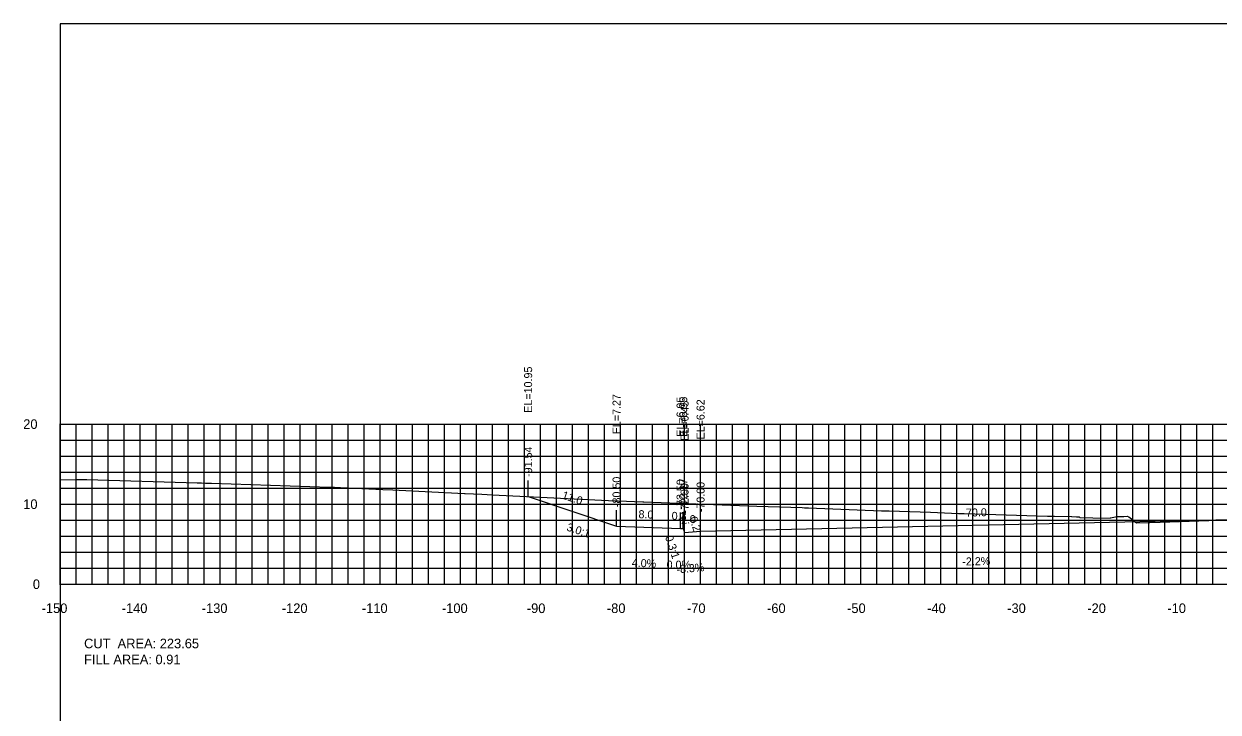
# Model space of a CAD drawing. Extents: x 1797419 to 1809236, y 248759 to 251512.
# Drawn here: x 1804856.5 to 1805005.6, y 250521.3 to 250607.3 of the extents above; entities that cross this region are included whole.
import ezdxf

# ---------------------------------------------------------------- set-up
doc = ezdxf.new("R2010")
doc.units = 0
for name, color, linetype in [('10', 7, 'Continuous'), ('3', 7, 'Continuous'), ('31', 7, 'Continuous'), ('4', 7, 'Continuous'), ('60', 7, 'Continuous'), ('ANNO-TXT', 7, 'Continuous'), ('CL-CNST', 7, 'Continuous'), ('Level 62', 7, 'Continuous'), ('M-ROADS', 7, 'Continuous')]:
    doc.layers.add(name, color=color, linetype=linetype)

msp = doc.modelspace()

# ---------------------------------------------------------------- linework, layer by layer
for p, q in [((1804919.46, 250548.21), (1804919.46, 250550.21)), ((1804930.5, 250544.52), (1804930.5, 250546.52)), ((1804938.5, 250544.2), (1804938.5, 250546.2)), ((1804938.83, 250544.2), (1804938.83, 250546.2)), ((1804939, 250543.7), (1804939, 250545.7)), ((1804941, 250543.87), (1804941, 250545.87))]:
    msp.add_line(p, q)
msp.add_lwpolyline([(1804861, 250417.26), (1805161, 250417.26), (1805161, 250607.26), (1804861, 250607.26)], close=True)
at = {"layer": '60'}
for p, q in [((1804860.94, 250557.26), (1804861, 250557.26)), ((1804861, 250537.26), (1804861, 250557.26)), ((1804860.94, 250547.26), (1804861, 250547.26)), ((1804860.94, 250537.26), (1804861, 250537.26)), ((1804861, 250537.26), (1805161, 250537.26)), ((1804861, 250537.2), (1804861, 250537.26)), ((1804871, 250537.2), (1804871, 250537.26)), ((1804881, 250537.2), (1804881, 250537.26)), ((1804891, 250537.2), (1804891, 250537.26)), ((1804901, 250537.2), (1804901, 250537.26)), ((1804911, 250537.2), (1804911, 250537.26)), ((1804921, 250537.2), (1804921, 250537.26)), ((1804931, 250537.2), (1804931, 250537.26)), ((1804941, 250537.2), (1804941, 250537.26)), ((1804951, 250537.2), (1804951, 250537.26)), ((1804961, 250537.2), (1804961, 250537.26)), ((1804971, 250537.2), (1804971, 250537.26)), ((1804981, 250537.2), (1804981, 250537.26)), ((1804991, 250537.2), (1804991, 250537.26)), ((1805001, 250537.2), (1805001, 250537.26))]:
    msp.add_line(p, q, dxfattribs=at)
at = {"layer": 'CL-CNST'}
msp.add_lwpolyline([(1804919.46, 250548.21), (1804930.5, 250544.52), (1804938.5, 250544.2), (1804938.83, 250544.2), (1804939, 250543.7), (1804941, 250543.87), (1805011, 250545.41), (1805081, 250543.89), (1805083, 250543.73), (1805083.17, 250544.23), (1805083.5, 250544.23), (1805085.5, 250544.31), (1805090.5, 250544.41), (1805091.5, 250544.45), (1805094.63, 250545.49)], dxfattribs=at)
at = {"layer": 'Level 62'}
for p, q in [((1804861, 250557.26), (1805161, 250557.26)), ((1804861, 250537.26), (1804861, 250557.26)), ((1804863, 250537.26), (1804863, 250557.26)), ((1804865, 250537.26), (1804865, 250557.26)), ((1804867, 250537.26), (1804867, 250557.26)), ((1804869, 250537.26), (1804869, 250557.26)), ((1804871, 250537.26), (1804871, 250557.26)), ((1804873, 250537.26), (1804873, 250557.26)), ((1804875, 250537.26), (1804875, 250557.26)), ((1804877, 250537.26), (1804877, 250557.26)), ((1804879, 250537.26), (1804879, 250557.26)), ((1804881, 250537.26), (1804881, 250557.26)), ((1804883, 250537.26), (1804883, 250557.26)), ((1804885, 250537.26), (1804885, 250557.26)), ((1804887, 250537.26), (1804887, 250557.26)), ((1804889, 250537.26), (1804889, 250557.26)), ((1804891, 250537.26), (1804891, 250557.26)), ((1804893, 250537.26), (1804893, 250557.26)), ((1804895, 250537.26), (1804895, 250557.26)), ((1804897, 250537.26), (1804897, 250557.26)), ((1804899, 250537.26), (1804899, 250557.26)), ((1804901, 250537.26), (1804901, 250557.26)), ((1804903, 250537.26), (1804903, 250557.26)), ((1804905, 250537.26), (1804905, 250557.26)), ((1804907, 250537.26), (1804907, 250557.26)), ((1804909, 250537.26), (1804909, 250557.26)), ((1804911, 250537.26), (1804911, 250557.26)), ((1804913, 250537.26), (1804913, 250557.26)), ((1804915, 250537.26), (1804915, 250557.26)), ((1804917, 250537.26), (1804917, 250557.26)), ((1804919, 250537.26), (1804919, 250557.26)), ((1804921, 250537.26), (1804921, 250557.26)), ((1804923, 250537.26), (1804923, 250557.26)), ((1804925, 250537.26), (1804925, 250557.26)), ((1804927, 250537.26), (1804927, 250557.26)), ((1804929, 250537.26), (1804929, 250557.26)), ((1804931, 250537.26), (1804931, 250557.26)), ((1804933, 250537.26), (1804933, 250557.26)), ((1804935, 250537.26), (1804935, 250557.26)), ((1804937, 250537.26), (1804937, 250557.26)), ((1804939, 250537.26), (1804939, 250557.26)), ((1804941, 250537.26), (1804941, 250557.26)), ((1804943, 250537.26), (1804943, 250557.26)), ((1804945, 250537.26), (1804945, 250557.26)), ((1804947, 250537.26), (1804947, 250557.26)), ((1804949, 250537.26), (1804949, 250557.26)), ((1804951, 250537.26), (1804951, 250557.26)), ((1804953, 250537.26), (1804953, 250557.26)), ((1804955, 250537.26), (1804955, 250557.26)), ((1804957, 250537.26), (1804957, 250557.26)), ((1804959, 250537.26), (1804959, 250557.26)), ((1804961, 250537.26), (1804961, 250557.26)), ((1804963, 250537.26), (1804963, 250557.26)), ((1804965, 250537.26), (1804965, 250557.26)), ((1804967, 250537.26), (1804967, 250557.26)), ((1804969, 250537.26), (1804969, 250557.26)), ((1804971, 250537.26), (1804971, 250557.26)), ((1804973, 250537.26), (1804973, 250557.26)), ((1804975, 250537.26), (1804975, 250557.26)), ((1804977, 250537.26), (1804977, 250557.26)), ((1804979, 250537.26), (1804979, 250557.26)), ((1804981, 250537.26), (1804981, 250557.26)), ((1804983, 250537.26), (1804983, 250557.26)), ((1804985, 250537.26), (1804985, 250557.26)), ((1804987, 250537.26), (1804987, 250557.26)), ((1804989, 250537.26), (1804989, 250557.26)), ((1804991, 250537.26), (1804991, 250557.26)), ((1804993, 250537.26), (1804993, 250557.26)), ((1804995, 250537.26), (1804995, 250557.26)), ((1804997, 250537.26), (1804997, 250557.26)), ((1804999, 250537.26), (1804999, 250557.26)), ((1805001, 250537.26), (1805001, 250557.26)), ((1805003, 250537.26), (1805003, 250557.26)), ((1805005, 250537.26), (1805005, 250557.26)), ((1804861, 250555.26), (1805161, 250555.26)), ((1804861, 250553.26), (1805161, 250553.26)), ((1804861, 250551.26), (1805161, 250551.26)), ((1804861, 250549.26), (1805161, 250549.26)), ((1804861, 250547.26), (1805161, 250547.26)), ((1804861, 250545.26), (1805161, 250545.26)), ((1804861, 250543.26), (1805161, 250543.26)), ((1804861, 250541.26), (1805161, 250541.26)), ((1804861, 250539.26), (1805161, 250539.26)), ((1804861, 250537.26), (1805161, 250537.26))]:
    msp.add_line(p, q, dxfattribs=at)
at = {"layer": 'M-ROADS'}
msp.add_lwpolyline([(1804861, 250550.31), (1804862.94, 250550.35), (1804863.07, 250550.35), (1804863.07, 250550.35), (1804863.08, 250550.36), (1804863.37, 250550.36), (1804863.42, 250550.36), (1804863.76, 250550.36), (1804864.1, 250550.35), (1804864.35, 250550.34), (1804878.12, 250549.93), (1804878.67, 250549.92), (1804878.68, 250549.92), (1804879.18, 250549.9), (1804879.83, 250549.89), (1804879.9, 250549.89), (1804894.66, 250549.38), (1804895.19, 250549.38), (1804895.26, 250549.38), (1804896.04, 250549.35), (1804901.32, 250549.09), (1804902.58, 250549.04), (1804903.36, 250549.01), (1804911.53, 250548.59), (1804911.59, 250548.58), (1804913.68, 250548.49), (1804914.99, 250548.42), (1804930.33, 250547.69), (1804930.38, 250547.69), (1804930.69, 250547.69), (1804933.79, 250547.55), (1804933.92, 250547.54), (1804948.01, 250547.03), (1804953.68, 250546.83), (1804953.98, 250546.82), (1804954.47, 250546.81), (1804963.6, 250546.44), (1804964.09, 250546.43), (1804964.57, 250546.42), (1804969.7, 250546.25), (1804973.23, 250546.1), (1804973.52, 250546.09), (1804973.92, 250546.08), (1804977.89, 250545.95), (1804984.34, 250545.77), (1804984.63, 250545.77), (1804985.22, 250545.76), (1804987.31, 250545.73), (1804987.36, 250545.73), (1804987.97, 250545.69), (1804988.29, 250545.69), (1804988.35, 250545.58), (1804989.98, 250545.54), (1804992.17, 250545.53), (1804992.21, 250545.57), (1804992.82, 250545.68), (1804993.08, 250545.72), (1804993.31, 250545.72), (1804993.43, 250545.72), (1804993.65, 250545.72), (1804993.79, 250545.72), (1804993.86, 250545.71), (1804994.3, 250545.76), (1804994.48, 250545.68), (1804994.83, 250545.42), (1804995.09, 250545.2), (1804995.43, 250544.93), (1804996.95, 250544.96), (1804996.99, 250544.96), (1804997.12, 250544.98), (1804997.13, 250544.98), (1804998.4, 250545.03), (1805009.31, 250545.39)], dxfattribs=at)

# ---------------------------------------------------------------- texts
for s, rotation, p in [('3.0:1', 341.5651, (1804924.19, 250543.99)), ('0.3:1', 288.4353, (1804936.55, 250543.16))]:
    msp.add_text(s, height=1, rotation=rotation).set_placement(p)
at = {"layer": '10'}
for s, p in [('-150', (1804858.7, 250533.66)), ('-140', (1804868.7, 250533.66)), ('-130', (1804878.7, 250533.66)), ('-120', (1804888.7, 250533.66)), ('-110', (1804898.7, 250533.66)), ('-100', (1804908.7, 250533.66)), ('-90', (1804919.3, 250533.66)), ('-80', (1804929.3, 250533.66)), ('-70', (1804939.3, 250533.66)), ('-60', (1804949.3, 250533.66)), ('-50', (1804959.3, 250533.66)), ('-40', (1804969.3, 250533.66)), ('-30', (1804979.3, 250533.66)), ('-20', (1804989.3, 250533.66)), ('-10', (1804999.3, 250533.66))]:
    msp.add_text(s, height=1.2, dxfattribs=at).set_placement(p)
at = {"layer": '3'}
for s, p in [('EL=10.95', (1804919.96, 250558.68)), ('EL=7.27', (1804931, 250555.99)), ('EL=6.95', (1804939, 250555.67)), ('EL=6.95', (1804939.33, 250555.67)), ('EL=6.62', (1804941.5, 250555.34)), ('EL=6.45', (1804939.5, 250555.17)), ('-91.54', (1804919.96, 250550.66)), ('-80.50', (1804931, 250546.9)), ('-72.50', (1804939, 250546.58)), ('-72.17', (1804939.33, 250546.66)), ('-72.00', (1804939.5, 250546.08)), ('-70.00', (1804941.5, 250546.25))]:
    msp.add_text(s, height=1, rotation=90, dxfattribs=at).set_placement(p)
at = {"layer": '31'}
for s, p in [('20', (1804856.4, 250556.66)), ('10', (1804856.4, 250546.66)), ('0', (1804857.6, 250536.66))]:
    msp.add_text(s, height=1.2, dxfattribs=at).set_placement(p)
at = {"layer": '4'}
for s, rotation, p in [('11.0', 341.5651, (1804923.6, 250547.98)), ('8.0', 357.7094, (1804933.23, 250545.52)), ('2.0', 4.7636, (1804938.59, 250544.77)), ('0.2', 288.4353, (1804939.56, 250545.52)), ('70.0', 1.2603, (1804974.16, 250545.7)), ('4.0%', 357.7094, (1804932.39, 250539.45)), ('-8.3%', 4.7636, (1804938.02, 250538.61)), ('-2.2%', 1.2603, (1804973.7, 250539.59))]:
    msp.add_text(s, height=1, rotation=rotation, dxfattribs=at).set_placement(p)
for s, p in [('0.3', (1804937.39, 250545.3)), ('0.0%', (1804936.76, 250539.2))]:
    msp.add_text(s, height=1, dxfattribs=at).set_placement(p)
at = {"layer": '60'}
msp.add_text('-', height=0.0001, dxfattribs=at).set_placement((1804861, 250537.26))
at = {"layer": 'ANNO-TXT'}
for s, p in [('CUT  AREA: 223.65', (1804864, 250529.26)), ('FILL AREA: 0.91', (1804864, 250527.26))]:
    msp.add_text(s, height=1.2, dxfattribs=at).set_placement(p)

doc.saveas('drawing.dxf')
